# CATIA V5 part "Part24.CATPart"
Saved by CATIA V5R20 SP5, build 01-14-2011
Part number: Part24
Material "Water": density 1000 kg/m3
Bounding box of the stored display mesh (mm): x -1.919 to 1.919, y -2 to 2, z -1.919 to 1.919
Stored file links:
  D:\新建文件夹\Part24.CATPart
  C:\Program Files\Dassault Systemes\B20\intel_a\startup\materials\Catalog.CATMaterial
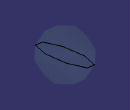
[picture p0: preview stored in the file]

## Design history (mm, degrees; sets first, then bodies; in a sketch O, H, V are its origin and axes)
Body1 (main body), material "Water"
  Sketch1 on xy-plane, origin (0, 0, 0), H (1, 0, 0), V (0, 1, 0)
    arc A1 centre (0, 0) radius 2 from (0, -2) to (0, 2) ccw
    axis line L1 (0, 5.9256) -> (0, -6.5373)
    point P1 (0, 5.9256)
    point P3 (0, 2)
    point P4 (0, -2)
    radius A1 = 2
    coincidence: P1 V, L1 P3, L1 P4
    vertical: L1 V
  Shaft1: profile Sketch1, axis Sketch1.L1, angle 360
